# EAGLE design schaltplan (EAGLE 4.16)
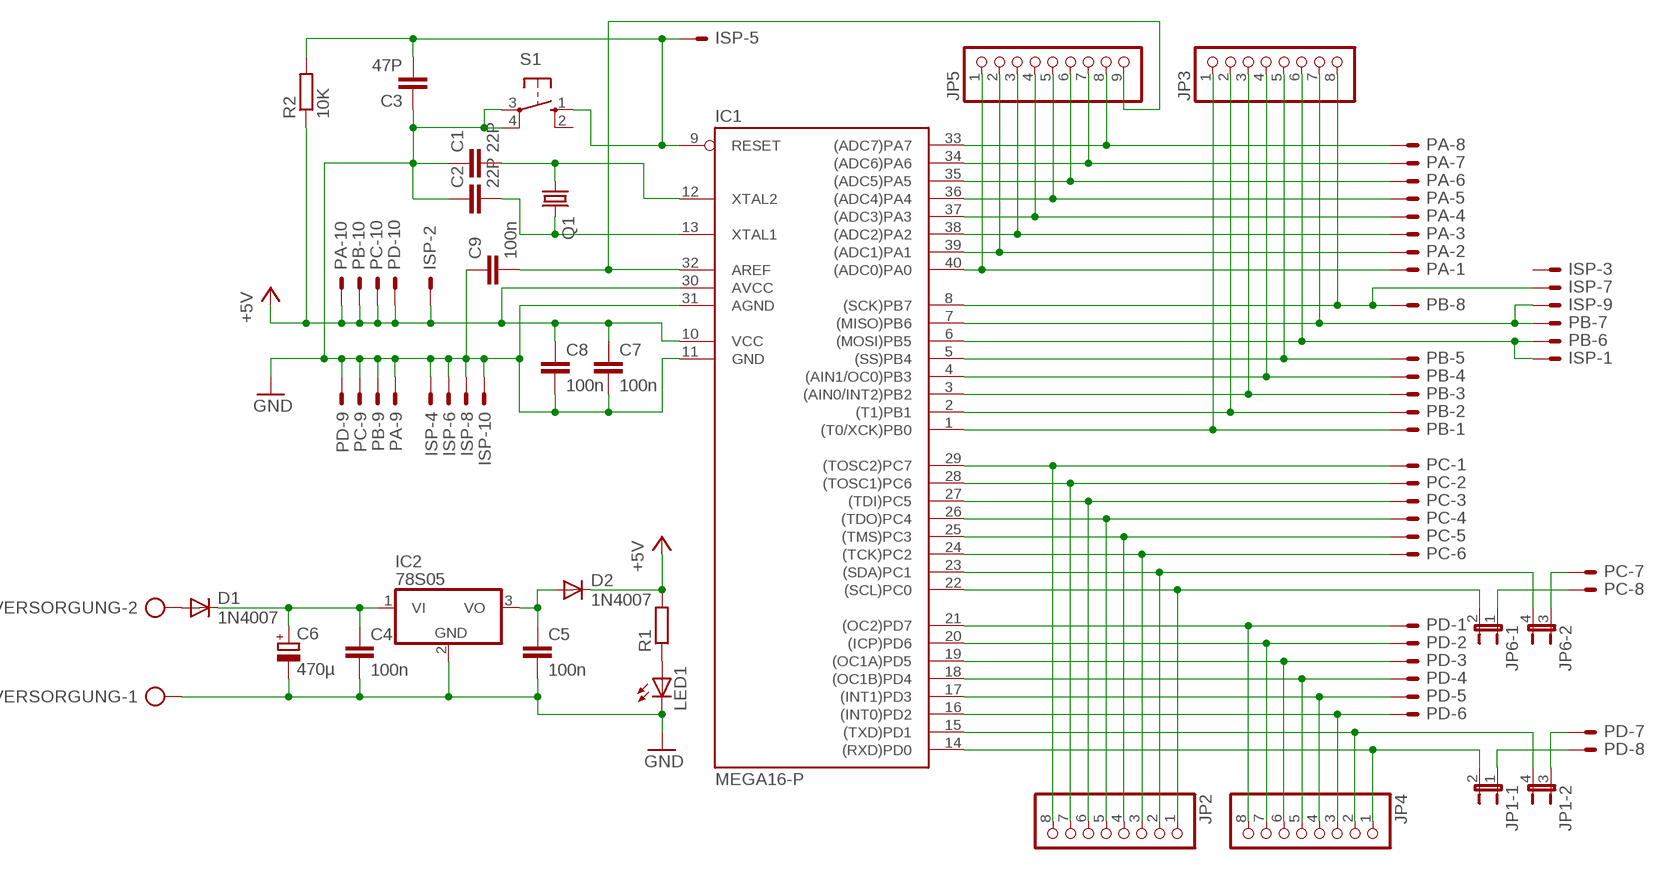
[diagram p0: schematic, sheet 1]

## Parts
C1  22P  C-EU025-024X044  [C025-024X044]
C2  22P  C-EU025-024X044  [C025-024X044]
C3  47P  C-EU025-024X044  [C025-024X044]
C4  100n  C-EU050-024X044  [C050-024X044]
C5  100n  C-EU025-024X044  [C025-024X044]
C6  470µ  CPOL-EUE30-10AXIAL  [E30-10]
C7  100n  C-EU025-024X044  [C025-024X044]
C8  100n  C-EU025-024X044  [C025-024X044]
C9  100n  C-EU025-024X044  [C025-024X044]
D1  1N4007  1N4004  [DO41-10]
D2  1N4007  1N4004  [DO41-10]
IC1  MEGA16-P  [DIL40]
IC2  78S05  7805T  [TO220H]
ISP  ML10E  [ML10]
JP1  JP2QE  [JP2Q]
JP2  PINHD-1X8  [1X08]
JP3  PINHD-1X8  [1X08]
JP4  PINHD-1X8  [1X08]
JP5  PINHD-1X9  [1X09]
JP6  JP2QE  [JP2Q]
LED1  LED5MM  [LED5MM]
PA  ML10E  [ML10]
PB  ML10E  [ML10]
PC  ML10E  [ML10]
PD  ML10E  [ML10]
Q1  CRYSTALHC18U-V  [HC18U-V]
R1  R-EU_0207/7  [0207/7]
R2  10K  R-EU_0207/7  [0207/7]
S1  10-XX  [B3F-10XX]
VERSORGUNG  AK500/2  [AK500/2]

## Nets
+5V: C7.1 C8.1 D2.C IC1.10(VCC) IC1.30(AVCC) ISP.2 PA.10 PB.10 PC.10 PD.10 R1.2 R2.1
GND: C1.1 C2.1 C3.1 C4.2 C5.2 C6.- C7.2 C8.2 C9.1 IC1.11(GND) IC1.31(AGND) IC2.2(GND) ISP.4 ISP.6 ISP.8 ISP.10 LED1.K(C) PA.9 PB.9 PC.9 PD.9 S1.3(P) S1.4(P1) VERSORGUNG.1
N$1: IC1.33((ADC7)PA7) JP5.8 PA.8
N$2: IC1.34((ADC6)PA6) JP5.7 PA.7
N$3: IC1.35((ADC5)PA5) JP5.6 PA.6
N$4: IC1.36((ADC4)PA4) JP5.5 PA.5
N$5: IC1.37((ADC3)PA3) JP5.4 PA.4
N$6: IC1.38((ADC2)PA2) JP5.3 PA.3
N$7: IC1.39((ADC1)PA1) JP5.2 PA.2
N$8: IC1.40((ADC0)PA0) JP5.1 PA.1
N$9: IC1.6((MOSI)PB5) ISP.1 JP3.6 PB.6
N$10: C4.1 C6.+ D1.C IC2.1(VI)
N$12: JP1.1 PD.8
N$13: JP1.3 PD.7
N$14: D1.A VERSORGUNG.2
N$15: IC1.2((T1)PB1) JP3.2 PB.2
N$16: IC1.1((T0/XCK)PB0) JP3.1 PB.1
N$17: IC1.29((TOSC2)PC7) JP2.8 PC.1
N$18: IC1.28((TOSC1)PC6) JP2.7 PC.2
N$19: IC1.27((TDI)PC5) JP2.6 PC.3
N$20: IC1.26((TDO)PC4) JP2.5 PC.4
N$21: IC1.25((TMS)PC3) JP2.4 PC.5
N$22: IC1.24((TCK)PC2) JP2.3 PC.6
N$23: IC1.23((SDA)PC1) JP2.2 JP6.4
N$24: IC1.22((SCL)PC0) JP2.1 JP6.2
N$25: IC1.21((OC2)PD7) JP4.8 PD.1
N$26: IC1.20((ICP)PD6) JP4.7 PD.2
N$27: IC1.19((OC1A)PD5) JP4.6 PD.3
N$28: IC1.18((OC1B)PD4) JP4.5 PD.4
N$29: IC1.17((INT1)PD3) JP4.4 PD.5
N$30: IC1.16((INT0)PD2) JP4.3 PD.6
N$31: IC1.15((TXD)PD1) JP1.4 JP4.2
N$32: IC1.14((RXD)PD0) JP1.2 JP4.1
N$33: C1.2 IC1.12(XTAL2) Q1.1
N$36: C2.2 IC1.13(XTAL1) Q1.2
N$37: C3.2 IC1.9(RESET) ISP.5 R2.2 S1.1(S)
N$38: LED1.A R1.1
N$39: JP6.3 PC.7
N$40: IC1.7((MISO)PB6) ISP.9 JP3.7 PB.7
N$41: IC1.8((SCK)PB7) ISP.7 JP3.8 PB.8
N$42: C9.2 IC1.32(AREF) JP5.9
N$43: JP6.1 PC.8
N$44: IC1.3((AIN0/INT2)PB2) JP3.3 PB.3
N$45: C5.1 D2.A IC2.3(VO)
N$46: IC1.4((AIN1/OC0)PB3) JP3.4 PB.4
N$47: IC1.5((SS)PB4) JP3.5 PB.5
Unconnected: ISP.3 S1.2(S1)

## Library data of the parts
C1-C5 C7-C9 = rcl:C-EU: CAPACITOR, European symbol
C6 = rcl:CPOL-EU: POLARIZED CAPACITOR, European symbol
D1 D2 = diode:1N4004: DIODE
IC1 = atmel:MEGA16-P: MICROCONTROLLER 16 Kbytes FLASH 1 kbytes SRAM 512 bytes EEPROM USART 8-channel 10 bit ADC Source: avr.lbr
IC2 = linear:78*: Positive VOLTAGE REGULATOR Source: http://cache.national.com/ds/LM/LM78L05.pdf http://www.fairchildsemi.com/ds/LM/LM7805.pdf
ISP PA PB PC PD = con-harting-ml:ML10?E: HARTING
JP1 JP6 = jumper:JP2QE: JUMPER
JP2-JP4 = pinhead:PINHD-1X8: PIN HEADER
JP5 = pinhead:PINHD-1X9: PIN HEADER
LED1 = led:LED: LED
Q1 = crystal:CRYSTAL: CRYSTAL
R1 R2 = rcl:R-EU_: RESISTOR, European symbol
S1 = switch-omron:10-XX: OMRON SWITCH
VERSORGUNG = con-ptr500:AK500/2: CONNECTOR

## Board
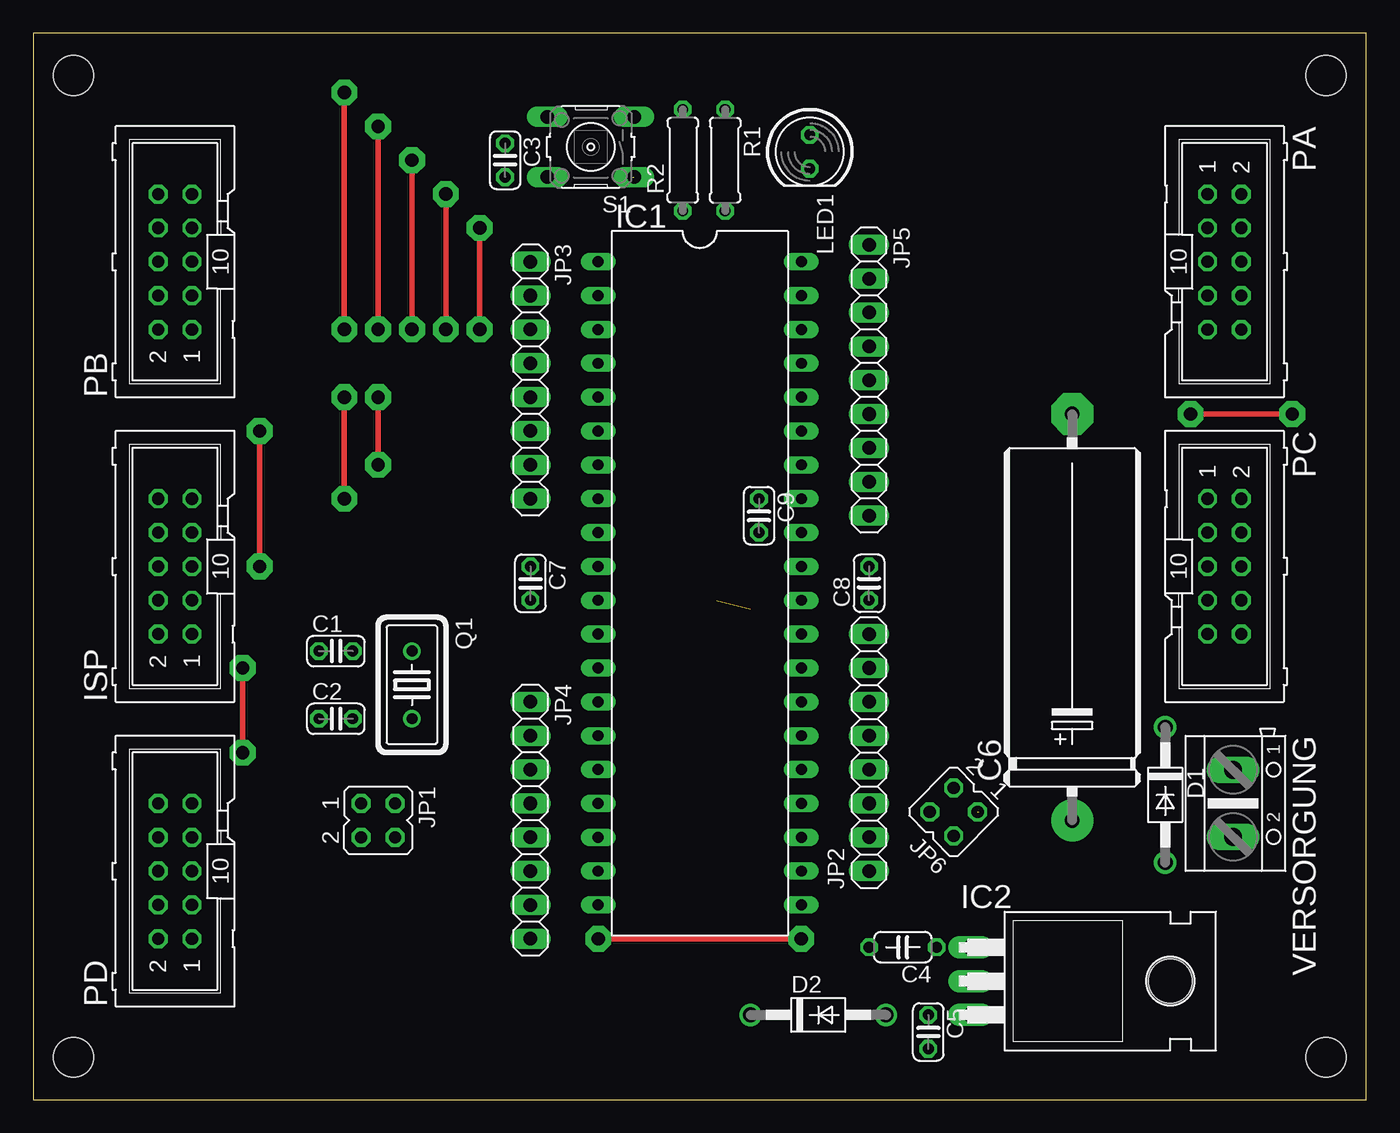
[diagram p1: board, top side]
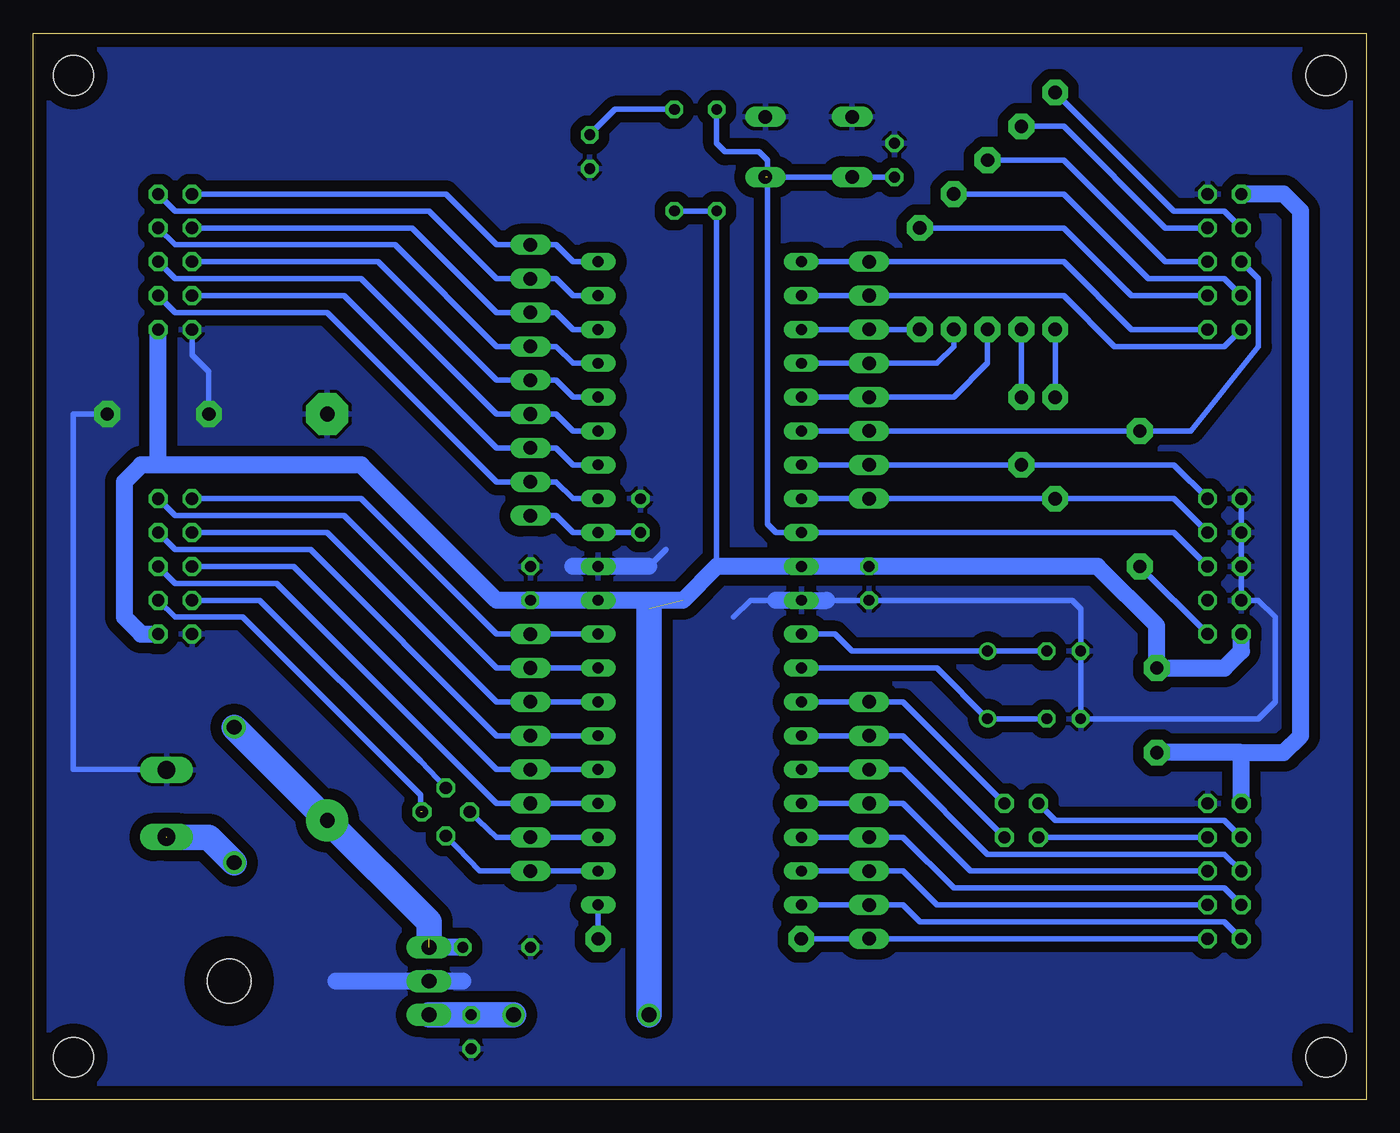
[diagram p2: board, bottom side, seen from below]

Size 100 x 80 mm. Coordinates in mm from the lower left corner, seen from the top.
Outline: 0,0 100,0 100,80 0,80 0,0
Copper layers (1*16): Top 0.035mm / dielectric 1.5mm / Bottom 0.035mm
Design rules "default": minimum track width 10mil, minimum drill 24mil, track to track 8mil, track to pad 8mil, pad to pad 8mil, via to via 8mil, smd to smd 8mil, copper to edge 40mil, drill to drill 8mil, minimum pad ring 10mil, minimum via ring 8mil, stop-mask expansion 4mil, vias tented up to drill 0mil, thermal gap 10mil
Holes 3 mm at 3.01,3.17 96.99,3.17 3.01,76.83 96.99,76.83

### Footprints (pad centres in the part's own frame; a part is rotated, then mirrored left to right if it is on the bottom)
C025-024X044 = drill 0.813 octagon: 1 -1.27,0; 2 1.27,0
C050-024X044 = drill 0.813 octagon: 1 -2.54,0; 2 2.54,0
E30-10 = drill 1.118 pad 3.15 round: + -15.24,0 | drill 1.118 pad 3.15 octagon: - 15.24,0
DO41-10 = drill 1.118 round: A 5.08,0; C -5.08,0
DIL40 = drill 0.813 long: 1 -24.13,-7.62; 2 -21.59,-7.62; 3 -19.05,-7.62; 4 -16.51,-7.62; 5 -13.97,-7.62; 6 -11.43,-7.62; 7 -8.89,-7.62; 8 -6.35,-7.62; 9 -3.81,-7.62; 10 -1.27,-7.62; 11 1.27,-7.62; 12 3.81,-7.62; 13 6.35,-7.62; 14 8.89,-7.62; 15 11.43,-7.62; 16 13.97,-7.62; 17 16.51,-7.62; 18 19.05,-7.62; 19 21.59,-7.62; 20 24.13,-7.62; 21 24.13,7.62; 22 21.59,7.62; 23 19.05,7.62; 24 16.51,7.62; 25 13.97,7.62; 26 11.43,7.62; 27 8.89,7.62; 28 6.35,7.62; 29 3.81,7.62; 30 1.27,7.62; 31 -1.27,7.62; 32 -3.81,7.62; 33 -6.35,7.62; 34 -8.89,7.62; 35 -11.43,7.62; 36 -13.97,7.62; 37 -16.51,7.62; 38 -19.05,7.62; 39 -21.59,7.62; 40 -24.13,7.62
TO220H = drill 1.118 long: 1 -2.54,-10.16; 2 0,-10.16; 3 2.54,-10.16 | hole 3.302: 0,4.826
ML10 = drill 0.914 octagon: 1 -5.08,-1.27; 2 -5.08,1.27; 3 -2.54,-1.27; 4 -2.54,1.27; 5 0,-1.27; 6 0,1.27; 7 2.54,-1.27; 8 2.54,1.27; 9 5.08,-1.27; 10 5.08,1.27
JP2Q = drill 0.914 octagon: 1 -1.27,-1.27; 2 -1.27,1.27; 3 1.27,-1.27; 4 1.27,1.27
1X08 = drill 1.016 long: 1 -8.89,0; 2 -6.35,0; 3 -3.81,0; 4 -1.27,0; 5 1.27,0; 6 3.81,0; 7 6.35,0; 8 8.89,0
1X09 = drill 1.016 long: 1 -10.16,0; 2 -7.62,0; 3 -5.08,0; 4 -2.54,0; 5 0,0; 6 2.54,0; 7 5.08,0; 8 7.62,0; 9 10.16,0
LED5MM = drill 0.813 octagon: A -1.27,0; K 1.27,0
HC18U-V = drill 0.813 round: 1 -2.54,0; 2 2.54,0
0207/7 = drill 0.813 octagon: 1 -3.81,0; 2 3.81,0
B3F-10XX = drill 1.016 long: 1 -3.251,2.261; 2 3.251,2.261; 3 -3.251,-2.261; 4 3.251,-2.261
AK500/2 = drill 1.321 long: 1 -2.515,0; 2 2.515,0

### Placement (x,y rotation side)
C1  22.7,33.65 0 top
C2  22.7,28.57 0 top
C3  35.39,70.48 270 top
C4  65.24,11.43 180 top
C5  67.14,5.08 270 top
C6  77.94,36.19 90 top
C7  37.3,38.73 270 top
C8  62.7,38.73 90 top
C9  54.45,43.81 270 top
D1  84.92,22.86 270 top
D2  58.89,6.34 0 top
IC1  50,38.73 270 top
IC2  80.48,8.89 270 top
ISP  10.63,40 90 top
JP1  25.87,20.95 270 top
JP2  62.7,26.03 90 top
JP3  37.3,53.97 270 top
JP4  37.3,20.95 270 top
JP5  62.7,53.97 270 top
JP6  69.05,21.58 135 top
LED1  58.25,71.11 270 top
PA  89.37,62.86 270 top
PB  10.63,62.86 90 top
PC  89.37,40 270 top
PD  10.63,17.14 90 top
Q1  28.41,31.11 270 top
R1  51.91,70.48 270 top
R2  48.73,70.48 90 top
S1  41.82,71.47 180 top
VERSORGUNG  90,22.22 270 top

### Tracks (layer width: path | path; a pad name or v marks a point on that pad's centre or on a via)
+5V  (via drill 1 pad 1.93)  (1 unrouted)
  Top 0.406: v15.71,26.03 v15.71,32.38
  Bottom 0.406: 48.73,40 R2.1 R1.2
  Bottom 1.27: ISP.2 9.36,33.65 10.63,32.38 v15.71,32.38 15.71,35.55 20.15,40 C7.1 IC1.10 48.73,40 51.27,37.46 IC1.30 C8.1 65.24,37.46 75.4,47.62 90.64,47.62 | 9.36,26.03 v15.71,26.03 | PD.10 9.36,26.03 | 9.36,26.03 6.18,26.03 4.92,27.3 4.92,66.67 6.18,67.94 PB.10 | 90.64,47.62 PA.10 | 90.64,47.62 91.91,47.62 93.18,46.35 93.18,36.19 91.91,34.92 PC.10
  Bottom 1.93: D2.C 53.81,36.83
GND  (via drill 1 pad 1.93)
  Top 0.406: v94.45,51.43 v86.83,51.43
  Bottom 0.406: ISP.10 ISP.4 8.09,37.46 6.82,36.19 6.82,29.84 8.09,28.57 C2.1 21.42,36.83 22.06,37.46 IC1.11 46.19,37.46 47.46,36.19 | 53.81,40 52.54,41.27 | PA.9 88.1,55.88 86.83,54.61 v86.83,51.43 | v94.45,51.43 96.99,51.43 96.99,24.76 90,24.76
  Bottom 1.27: 53.81,40 IC1.31 59.52,40 | 44.28,37.46 IC1.11 40.48,37.46 | IC2.2 72.22,8.89 | 67.78,8.89 IC2.2 | IC2.2 77.3,8.89
  pour Bottom (isolate 0.813): 0.47,0.63 0.47,79.37 99.53,79.37 99.53,0.63
N$1
  Bottom 0.406: IC1.33 59.52,45.08 60.8,46.35 JP5.8 65.24,46.35 77.94,59.05 89.37,59.05 PA.8
N$2
  Bottom 0.406: IC1.34 59.52,47.62 60.8,48.89 JP5.7 65.24,48.89 76.67,60.32 PA.7
N$3
  Bottom 0.406: IC1.35 59.52,50.16 60.8,51.43 JP5.6 65.24,51.43 75.4,61.59 89.37,61.59 PA.6
N$4
  Bottom 0.406: IC1.36 59.52,52.7 60.8,53.97 JP5.5 65.24,53.97 74.13,62.86 PA.5
N$5
  Bottom 0.406: IC1.37 59.52,55.24 60.8,56.51 JP5.4 65.24,56.51 72.86,64.13 89.37,64.13 PA.4
N$6
  Bottom 0.406: IC1.38 59.52,57.78 60.8,59.05 JP5.3 65.24,59.05 71.59,65.4 PA.3
N$7
  Bottom 0.406: IC1.39 59.52,60.32 60.8,61.59 JP5.2 65.24,61.59 70.32,66.67 89.37,66.67 PA.2
N$8
  Bottom 0.406: IC1.40 59.52,62.86 60.8,64.13 JP5.1 65.24,64.13 69.05,67.94 PA.1
N$9  (via drill 1 pad 1.93)
  Top 0.406: v16.98,40 v16.98,50.16
  Bottom 0.406: ISP.1 v16.98,40 | PB.6 8.09,61.59 8.09,56.51 13.17,50.16 v16.98,50.16 JP3.6 IC1.6
N$10  (1 unrouted)
  Bottom 1.27: C4.1 IC2.1
  Bottom 1.93: D1.C C6.+ 70.32,13.33 70.32,12.06
N$12
  Bottom 0.406: JP1.1 23.33,20.95 10.63,20.95 PD.8
N$13
  Bottom 0.406: PD.7 JP1.3
N$14  (1 unrouted)
  Bottom 1.93: 90,19.68 86.83,19.68 D1.A
N$15
  Bottom 0.406: PB.2 10.63,56.51 18.88,56.51 22.7,60.32 JP3.2 IC1.2
N$16
  Bottom 0.406: PB.1 17.61,57.78 22.7,62.86 JP3.1 IC1.1
N$17
  Bottom 0.406: IC1.29 JP2.8 65.24,34.92 75.4,45.08 PC.1
N$18
  Bottom 0.406: IC1.28 JP2.7 65.24,32.38 76.67,43.81 89.37,43.81 PC.2
N$19
  Bottom 0.406: IC1.27 JP2.6 65.24,29.84 77.94,42.54 PC.3
N$20
  Bottom 0.406: IC1.26 JP2.5 65.24,27.3 79.21,41.27 89.37,41.27 PC.4
N$21
  Bottom 0.406: IC1.25 JP2.4 65.24,24.76 80.48,40 PC.5
N$22
  Bottom 0.406: IC1.24 JP2.3 65.24,22.22 81.75,38.73 89.37,38.73 PC.6
N$23
  Bottom 0.406: IC1.23 JP2.2 65.24,19.68 JP6.4
N$24
  Bottom 0.406: IC1.22 JP2.1 66.51,17.14 JP6.2
N$25  (via drill 1 pad 1.93)
  Top 0.406: v42.38,12.06 v57.62,12.06
  Bottom 0.406: PD.1 JP4.8 v42.38,12.06 43.02,12.06 | v57.62,12.06 IC1.21
N$26
  Bottom 0.406: IC1.20 JP4.7 34.76,14.6 33.49,13.33 10.63,13.33 PD.2
N$27
  Bottom 0.406: IC1.19 JP4.6 34.76,17.14 32.22,14.6 PD.3
N$28
  Bottom 0.406: IC1.18 JP4.5 34.76,19.68 30.95,15.87 10.63,15.87 PD.4
N$29
  Bottom 0.406: IC1.17 JP4.4 34.76,22.22 29.68,17.14 PD.5
N$30
  Bottom 0.406: IC1.16 JP4.3 34.76,24.76 28.41,18.41 10.63,18.41 PD.6
N$31
  Bottom 0.406: JP1.4 34.76,27.3 JP4.2 IC1.15
N$32
  Bottom 0.406: JP1.2 34.76,29.84 JP4.1 IC1.14
N$33
  Bottom 0.406: IC1.12 39.84,34.92 38.57,33.65 Q1.1 C1.2
N$36
  Bottom 0.406: IC1.13 32.22,32.38 Q1.2 C2.2
N$37  (1 unrouted)
  Bottom 0.406: ISP.5 14.44,42.54 IC1.9 44.28,42.54 44.92,43.18 44.92,69.21 | 44.92,69.21 C3.2 | 44.92,69.21 44.92,70.48 45.55,71.11 48.09,71.11 48.73,71.75 R2.2
N$38
  Bottom 0.406: R1.1 56.35,74.29 LED1.A
N$39
  Bottom 0.406: JP6.3 70.95,25.39 83.02,37.46 PC.7
N$40  (via drill 1 pad 1.93)
  Top 0.406: v25.87,57.78 v25.87,73.02 | v25.87,47.62 v25.87,52.7
  Bottom 0.406: v25.87,73.02 22.7,73.02 15.08,65.4 PB.7 | ISP.9 14.44,47.62 v25.87,47.62 JP3.7 IC1.7 | v25.87,52.7 v25.87,57.78
N$41  (via drill 1 pad 1.93)
  Top 0.406: v23.33,57.78 v23.33,75.56 | v23.33,45.08 v23.33,52.7
  Bottom 0.406: v23.33,75.56 14.44,66.67 10.63,66.67 PB.8 | ISP.7 14.44,45.08 v23.33,45.08 JP3.8 IC1.8 | v23.33,52.7 v23.33,57.78
N$42
  Bottom 0.406: C9.2 IC1.32 59.52,42.54 60.8,43.81 JP5.9
N$43  (1 unrouted)
  Bottom 0.406: 70.95,21.58 70.95,22.86 84.29,36.19 89.37,36.19 PC.8
N$44  (via drill 1 pad 1.93)
  Top 0.406: v33.49,65.4 v33.49,57.78
  Bottom 0.406: v33.49,65.4 22.7,65.4 17.61,60.32 PB.3 | IC1.3 JP3.3 v33.49,57.78
N$45
  Bottom 1.93: IC2.3 C5.1 D2.A
N$46  (via drill 1 pad 1.93)
  Top 0.406: v30.95,67.94 v30.95,57.78
  Bottom 0.406: v30.95,67.94 22.7,67.94 16.34,61.59 10.63,61.59 PB.4 | v30.95,57.78 30.95,56.51 32.22,55.24 JP3.4 IC1.4
N$47  (via drill 1 pad 1.93)
  Top 0.406: v28.41,70.48 v28.41,57.78
  Bottom 0.406: v28.41,70.48 22.7,70.48 15.08,62.86 PB.5 | v28.41,57.78 28.41,55.24 30.95,52.7 JP3.5 IC1.5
